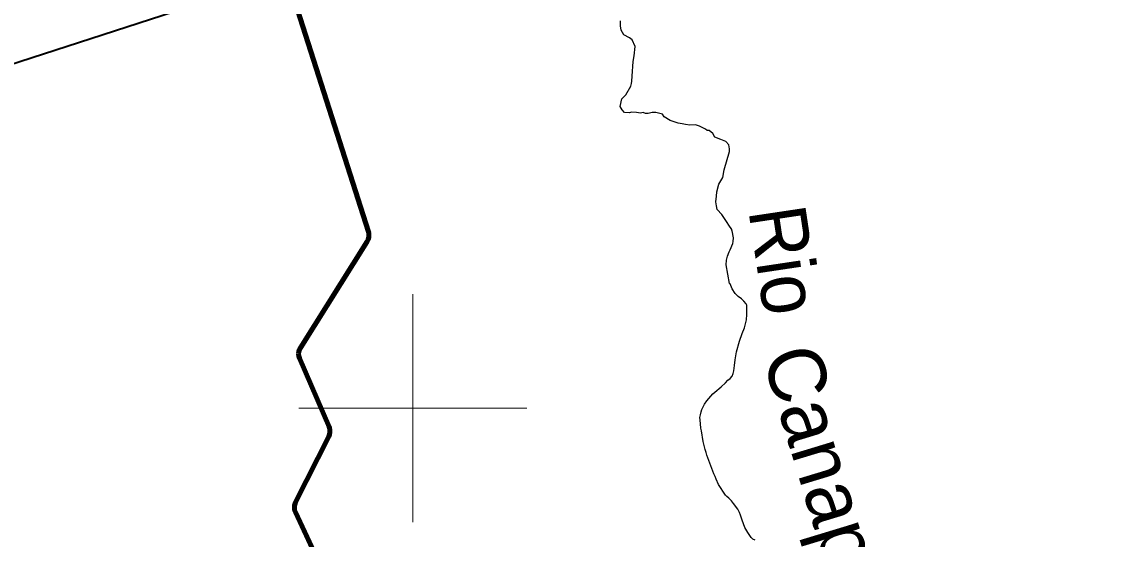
# Model space of a CAD drawing. Extents: x 553962 to 842807, y 8883888 to 9032388.
# Drawn here: x 646568 to 656083, y 8973850 to 8978389 of the extents above; entities that cross this region are included whole.
import ezdxf
from ezdxf.enums import TextEntityAlignment as Align

# ---------------------------------------------------------------- set-up
doc = ezdxf.new("R2010")
doc.units = 0
doc.header["$LTSCALE"] = 200
doc.linetypes.add('DOT_DASHED', pattern=[7.7, 5, -1.2, 0.3, -1.2])
for name, color, linetype, lineweight in [('12', 7, 'Continuous', 25), ('2', 7, 'Continuous', 13), ('24', 7, 'Continuous', 25), ('7', 7, 'Continuous', 90)]:
    doc.layers.add(name, color=color, linetype=linetype, lineweight=lineweight)
doc.layers.add('49', color=7, linetype='Continuous')

msp = doc.modelspace()

# ---------------------------------------------------------------- linework, layer by layer
at = {"layer": '12', "lineweight": 40}
msp.add_line((636526.5, 8974783.6), (662912, 8983353), dxfattribs=at)
at = {"layer": '2'}
for p, q in [((650000, 8974000), (650000, 8976000)), ((649000, 8975000), (651000, 8975000))]:
    msp.add_line(p, q, dxfattribs=at)
at = {"layer": '24'}
for points in [[(652771.6, 8977307.6), (652743.6, 8977336.7), (652700, 8977355.6), (652648.8, 8977376.5), (652631.7, 8977406.9), (652599.1, 8977434.4), (652582.3, 8977435.4), (652567.8, 8977444.9), (652514, 8977471.5), (652479.8, 8977484.8), (652430.5, 8977481), (652391.1, 8977486.8), (652363.3, 8977492), (652326.1, 8977499.9), (652255.9, 8977522.7), (652202.8, 8977555), (652189.5, 8977577.8), (652130.7, 8977591.1), (652098.4, 8977593), (652062.3, 8977583.5), (652039.6, 8977583.5), (652020.6, 8977593), (651997.8, 8977587.3), (651961.8, 8977593), (651916.2, 8977594.9), (651899.2, 8977589.2), (651855.5, 8977591.1), (651834.4, 8977616.2), (651817.7, 8977643.9), (651832.7, 8977712.6), (651866.9, 8977748.7), (651911.5, 8977823.3), (651916.2, 8977847.4), (651920, 8977866.4), (651923.8, 8977910.1), (651933.3, 8978039.2), (651940.9, 8978090.4), (651948.5, 8978170.2), (651923.8, 8978229), (651901.1, 8978248), (651851.2, 8978272.3), (651826.5, 8978315.8), (651820.6, 8978351), (651819.5, 8978396.3)], [(652778.6, 8977249), (652777.9, 8977274.4), (652771.6, 8977307.6)], [(652799.8, 8975280.4), (652809.8, 8975302.2), (652816.1, 8975328.3), (652822.4, 8975374.6), (652826.9, 8975422.5), (652839.8, 8975493.2), (652864.5, 8975587.5), (652888.2, 8975655.6), (652908, 8975704.5), (652925.9, 8975773.4), (652929.4, 8975820.5), (652930.5, 8975902.1), (652923, 8975914.4), (652902.1, 8975937.5), (652881.4, 8975957.1), (652852.2, 8975978.9), (652827.9, 8976005.5), (652801.9, 8976045.7), (652783.3, 8976090.1), (652777.5, 8976093.8), (652748.7, 8976257.8), (652752.2, 8976297.8), (652759.6, 8976332.9), (652774.2, 8976369.2), (652784.3, 8976387.2), (652805.5, 8976443.3), (652809.5, 8976460.7), (652811.3, 8976493), (652801.1, 8976555.8), (652798.8, 8976558), (652796.5, 8976566.6), (652771.4, 8976603.6), (652757.2, 8976628.1), (652709.4, 8976696.7), (652669.3, 8976741.1), (652663.9, 8976773), (652657.8, 8976807.6), (652663.9, 8976859.5), (652664.9, 8976895.8), (652682.2, 8976964.3), (652718.6, 8977021.2), (652730, 8977089.5), (652778.6, 8977249)], [(653002.9, 8973840.6), (652981, 8973851.6), (652965.9, 8973864.6), (652937, 8973909.3), (652911.1, 8973953), (652887.5, 8974017.3), (652874.5, 8974060.1), (652864.8, 8974083.7), (652850.2, 8974112.8), (652813.3, 8974163.9), (652794.5, 8974187.8), (652771, 8974210.2), (652753.5, 8974223.6), (652741.1, 8974236.2), (652681.1, 8974329.2), (652660, 8974375.6), (652651, 8974399.9), (652639.3, 8974423.5), (652623.5, 8974469.8), (652603.2, 8974516.9), (652579.3, 8974588.4), (652572.8, 8974612), (652562.8, 8974637.3), (652546.2, 8974706.2), (652532.2, 8974799.6), (652526.8, 8974824.9), (652519.2, 8974897.6), (652518.3, 8974918.3), (652521.3, 8974941), (652527.4, 8974967.1), (652535.4, 8974989), (652558, 8975036.1), (652577.2, 8975063.9), (652631.7, 8975125.9), (652648.1, 8975141.2), (652704.5, 8975187.2), (652741, 8975221.5), (652762.8, 8975244.2), (652783.3, 8975259.7), (652799.8, 8975280.4)]]:
    msp.add_lwpolyline(points, dxfattribs=at)
at = {"layer": '7'}
for points in [[(648997.5, 8975475.9), (648999.4, 8975495.8), (649005.2, 8975514.9), (649012.9, 8975529.8), (649599.2, 8976460.8), (649608.1, 8976478.7), (649613.2, 8976498), (649614.5, 8976517.9), (649611.7, 8976537.7), (649609.8, 8976544.5), (648760.2, 8979209.5), (648756, 8979229.1), (648755.9, 8979249), (648759.7, 8979268.6), (648765.1, 8979282.8), (648947.1, 8979666.4)], [(648997.5, 8975475.9), (648999.4, 8975495.8), (649005.2, 8975514.9), (649012.9, 8975529.8), (649599.2, 8976460.8), (649608.1, 8976478.7), (649613.2, 8976498), (649614.5, 8976517.9), (649611.7, 8976537.7), (649609.8, 8976544.5), (648760.2, 8979209.5), (648756, 8979229.1), (648755.9, 8979249), (648759.7, 8979268.6), (648765.1, 8979282.8), (648947.1, 8979666.4)], [(649254.1, 8973479.3), (648969, 8974087), (648962.3, 8974105.8), (648959.6, 8974125.6), (648960.8, 8974145.6), (648966, 8974164.9), (648970.3, 8974174.6), (649261.4, 8974750.4), (649268.6, 8974769), (649271.9, 8974788.7), (649271.3, 8974808.7), (649266.7, 8974828.1), (649264, 8974834.9), (649005.6, 8975437), (648999.6, 8975456.1), (648997.5, 8975475.9)]]:
    msp.add_lwpolyline(points, dxfattribs=at)
at = {"layer": '7', "linetype": 'DOT_DASHED'}
msp.add_lwpolyline([(649254.1, 8973479.3), (648969, 8974087), (648962.3, 8974105.8), (648959.6, 8974125.6), (648960.8, 8974145.6), (648966, 8974164.9), (648970.3, 8974174.6), (649261.4, 8974750.4), (649268.6, 8974769), (649271.9, 8974788.7), (649271.3, 8974808.7), (649266.7, 8974828.1), (649264, 8974834.9), (649005.6, 8975437), (648999.6, 8975456.1), (648997.5, 8975475.9)], dxfattribs=at)

# ---------------------------------------------------------------- texts
at = {"layer": '49', "width": 0.95}
msp.add_text('Rio', height=500, rotation=278.527, dxfattribs=at).set_placement((653013, 8976261.9), align=Align.CENTER)
at = {"layer": '49'}
msp.add_text('Canapi', height=500, rotation=286.879, dxfattribs=at).set_placement((653368, 8974444.7), align=Align.CENTER)

doc.saveas('drawing.dxf')
